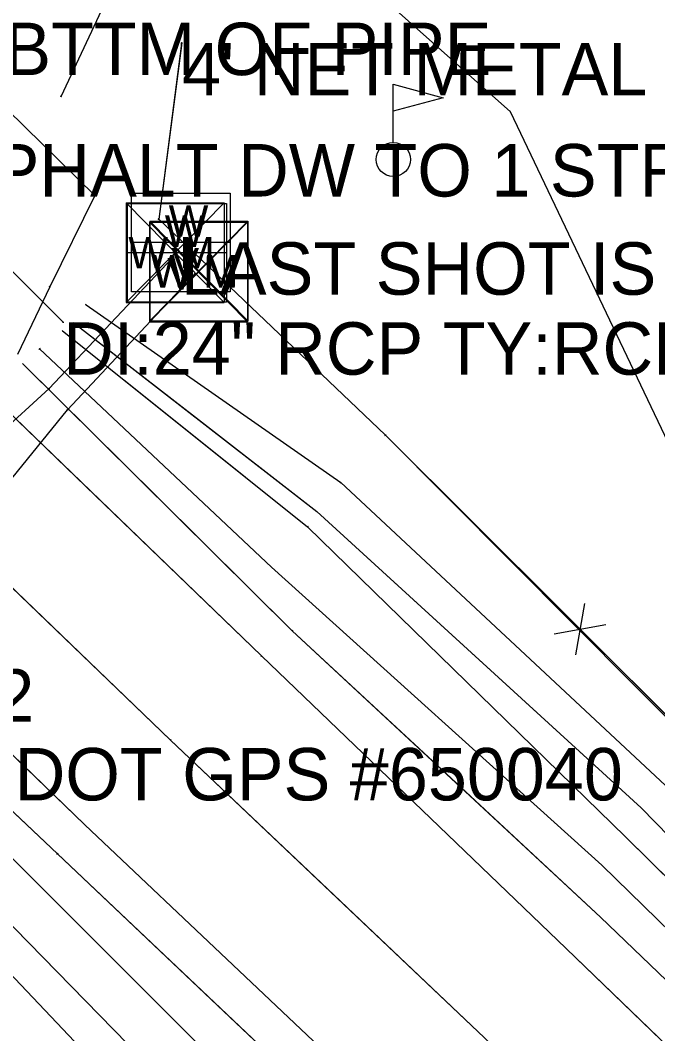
# Model space of a CAD drawing. Extents: x -99999 to 591807, y -99999 to 347168.
# Drawn here: x 588252.2 to 588313, y 346221.5 to 346318.1 of the extents above; entities that cross this region are included whole.
import ezdxf

# ---------------------------------------------------------------- set-up
doc = ezdxf.new("R2010")
doc.units = 0
for name, color, linetype in [('S_BREAKLINE', 7, 'Continuous'), ('S_DITCHLINE', 7, 'Continuous'), ('S_DRG_PT_SYM', 7, 'Continuous'), ('S_DRIVEWAY', 7, 'Continuous'), ('S_EDGE_PAVEMENT', 7, 'Continuous'), ('S_FENCE', 7, 'Continuous'), ('S_FENCE_ANNOT', 7, 'Continuous'), ('S_FLAG_POLE', 7, 'Continuous'), ('S_GRD_PT_SYM', 7, 'Continuous'), ('S_MSC_PT_SYM', 7, 'Continuous'), ('S_PAVEMENT_CROWN', 7, 'Continuous'), ('S_PRIMARY_CTL_ANNOT', 7, 'Continuous'), ('S_RDW_PT_SYM', 7, 'Continuous'), ('S_SHOULDER', 7, 'Continuous'), ('S_SIDE_DRAIN', 7, 'Continuous'), ('S_SIDE_DRAIN_ANNOT', 7, 'Continuous'), ('S_SURVEY_TEXT_ANNOT', 7, 'Continuous'), ('S_UTL_PT_SYM', 7, 'Continuous'), ('S_WATER_UTILITIES', 7, 'Continuous'), ('S_WATER_UTILITIES_ANNOT', 7, 'Continuous')]:
    doc.layers.add(name, color=color, linetype=linetype)

msp = doc.modelspace()

# ---------------------------------------------------------------- linework, layer by layer
at = {"layer": 'S_BREAKLINE'}
for points in [[(587985.007, 346494.142), (588043.408, 346436.277), (588108.559, 346374.608), (588173.852, 346311.357), (588242.383, 346247.25), (588302.697, 346186.986), (588369.158, 346122.224), (588383.207, 346097.167), (588432.308, 346045.452), (588485.71, 345983.723), (588533.051, 345919.601)], [(587978.947, 346487.853), (588038.255, 346431.024), (588103.615, 346368.923), (588168.93, 346306.428), (588237.999, 346241.179), (588296.132, 346179.846), (588360.541, 346112.54), (588377.938, 346092.952), (588425.834, 346037.788), (588477.63, 345977.565), (588525.633, 345916.464)], [(588270.945, 346334.356), (588298.929, 346309.423), (588316.919, 346271.712), (588387.51, 346208.813), (588441.295, 346152.589), (588498.26, 346098.506), (588551.789, 346050.318), (588556.498, 346044.431)], [(588267.583, 346315.916), (588265.419, 346299.156), (588287.028, 346278.583), (588316.874, 346248.579), (588343.915, 346221.838), (588373.42, 346192.774), (588395.235, 346170.529), (588420.015, 346145.892), (588449.803, 346115.64), (588486.713, 346078.801), (588522.482, 346044.903), (588554.838, 346014.155), (588576.029, 345995.146)], [(588258.499, 346290.999), (588282.77, 346274.06), (588314.166, 346244.765), (588341.56, 346217.857), (588369.119, 346190.732), (588392.899, 346168.316), (588418.339, 346141.705), (588447.624, 346113.302), (588484.571, 346076.998), (588520.035, 346043.233), (588550.34, 346012.541), (588575.477, 345989.737), (588578.825, 345983.151)], [(588254.073, 346286.789), (588276.179, 346265.976), (588307.663, 346237.576), (588332.885, 346212.93), (588360.879, 346185.108), (588386.622, 346162.852), (588413.054, 346137.046), (588442.353, 346107.702), (588480.664, 346072.643), (588515.171, 346038.537), (588542.869, 346006.756), (588564.232, 345981.492), (588590.975, 345941.879), (588596.766, 345935.725)]]:
    msp.add_lwpolyline(points, dxfattribs=at)
at = {"layer": 'S_DITCHLINE'}
for points in [[(587981.381, 346490.489), (588040.721, 346433.289), (588105.81, 346371.994), (588170.92, 346308.422), (588239.535, 346243.967), (588298.867, 346183.241), (588365.047, 346118.269), (588381.602, 346095.516), (588429.365, 346040.978), (588482.843, 345982.856), (588529.718, 345920.184), (588552.998, 345879.12), (588569.51, 345828.652), (588585.869, 345761.878), (588598.499, 345693.111), (588612.58, 345591.707), (588620.738, 345530.501), (588634.946, 345464.485), (588639.413, 345427.117), (588638.596, 345425.107)], [(588154.643, 346324.315), (588170.92, 346308.422), (588188.074, 346292.308), (588205.228, 346276.194), (588222.381, 346260.081), (588239.535, 346243.967), (588254.368, 346228.786), (588269.201, 346213.604), (588284.034, 346198.423), (588298.867, 346183.241), (588315.412, 346166.998), (588331.957, 346150.755), (588348.502, 346134.512), (588365.047, 346118.269), (588373.324, 346106.893)], [(588256.25, 346288.517), (588279.619, 346269.831), (588309.927, 346240.279), (588334.152, 346216.38), (588364.162, 346188.465), (588374.07, 346176.5), (588389.177, 346164.467), (588414.617, 346138.085), (588443.666, 346108.884), (588482.064, 346074.03), (588517.386, 346040.35), (588546.168, 346009.017), (588569.054, 345985.248), (588580.187, 345969.799), (588596.13, 345945.066), (588601.107, 345940.145)], [(588256.25, 346288.517), (588267.934, 346279.174), (588279.619, 346269.831), (588294.773, 346255.055), (588309.927, 346240.279), (588322.039, 346228.33), (588334.152, 346216.38), (588349.157, 346202.423), (588364.162, 346188.465), (588374.07, 346176.5)], [(588257.348, 346289.253), (588280.504, 346271.298), (588311.415, 346243.027), (588335.923, 346217.957), (588365.97, 346190.072), (588375.966, 346178.271), (588390.647, 346166.994), (588416.359, 346140.222), (588445.778, 346111.154), (588483.301, 346075.522), (588519.201, 346042.047), (588548.233, 346010.867), (588571.043, 345986.23), (588581.118, 345970.703), (588597.815, 345946.583), (588601.9, 345941.764), (588631.023, 345942.625), (588635.559, 345948.641), (588633.328, 345950.725), (588636.714, 345965.196), (588640.069, 345982.317), (588641.424, 345998.377)], [(588257.348, 346289.253), (588268.926, 346280.276), (588280.504, 346271.298), (588295.959, 346257.163), (588311.415, 346243.027), (588323.669, 346230.492), (588335.923, 346217.957), (588350.946, 346204.014), (588365.97, 346190.072), (588375.966, 346178.271)]]:
    msp.add_lwpolyline(points, dxfattribs=at)
at = {"layer": 'S_DRG_PT_SYM'}
msp.add_lwpolyline([(588256.311, 346289.338), (588256.311, 346289.388), (588256.311, 346289.338), (588256.261, 346289.338), (588256.311, 346289.338), (588256.311, 346289.288), (588256.311, 346289.338), (588256.361, 346289.338)], dxfattribs=at)
at = {"layer": 'S_DRIVEWAY'}
for points in [[(588256.111, 346310.878), (588262.684, 346324.856), (588278.363, 346353.936), (588300.6, 346391.67), (588311.856, 346406.55)], [(588256.111, 346310.878), (588262.684, 346324.856), (588270.523, 346339.396), (588278.363, 346353.936), (588289.481, 346372.803), (588300.6, 346391.67), (588311.856, 346406.55)], [(588224.078, 346312.27), (588231.601, 346312.394), (588239.988, 346317.557), (588249.265, 346311.269), (588259.341, 346301.433), (588255.039, 346292.72), (588251.962, 346286.264)], [(588224.078, 346312.27), (588231.601, 346312.394), (588239.988, 346317.557), (588249.265, 346311.269), (588259.341, 346301.433), (588255.039, 346292.72), (588251.962, 346286.264)]]:
    msp.add_lwpolyline(points, dxfattribs=at)
at = {"layer": 'S_EDGE_PAVEMENT'}
for points in [[(588006.506, 346515.665), (588037.252, 346486.281), (588068.965, 346456.074), (588098.412, 346427.99), (588126.486, 346401.048), (588156.062, 346372.419), (588184.379, 346345.174), (588213.093, 346317.554), (588241.735, 346289.831), (588275.211, 346257.515), (588304.275, 346229.616), (588334.125, 346200.795), (588363.948, 346171.697), (588391.179, 346144.843), (588419.554, 346117.127), (588447.946, 346088.704), (588472.864, 346062.771), (588495.2, 346037.929), (588515.958, 346012.839), (588538.304, 345983.933), (588553.852, 345961.476), (588569.437, 345935.938), (588581.549, 345913.628)], [(587990.039, 346499.659), (588021.444, 346469.827), (588052.982, 346439.412), (588082.26, 346411.475), (588110.157, 346384.471), (588139.714, 346355.894), (588167.475, 346329.092), (588196.939, 346300.739), (588228.679, 346270.069), (588258.368, 346241.406), (588287.791, 346213.567), (588317.296, 346184.82), (588347.777, 346154.949), (588374.652, 346128.542), (588403.229, 346100.418), (588430.525, 346072.999), (588454.75, 346047.655), (588476.4, 346023.753), (588497.807, 345997.867), (588518.495, 345970.798), (588533.243, 345949.774), (588549.253, 345924.479)], [(588198.736, 346331.364), (588213.093, 346317.554), (588227.414, 346303.693), (588241.735, 346289.831), (588258.473, 346273.673), (588275.211, 346257.515), (588289.743, 346243.566), (588304.275, 346229.616), (588319.2, 346215.206), (588334.125, 346200.795), (588349.036, 346186.246), (588363.948, 346171.697), (588377.564, 346158.27)], [(588167.475, 346329.092), (588182.207, 346314.916), (588196.939, 346300.739), (588212.809, 346285.404), (588228.679, 346270.069), (588243.524, 346255.738), (588258.368, 346241.406), (588273.08, 346227.487), (588287.791, 346213.567), (588302.544, 346199.194), (588317.296, 346184.82), (588332.537, 346169.885), (588347.777, 346154.949), (588361.215, 346141.746), (588374.652, 346128.542)]]:
    msp.add_lwpolyline(points, dxfattribs=at)
at = {"layer": 'S_FENCE'}
for p, q in [((588267.635, 346315.977), (588265.419, 346299.156)), ((588265.419, 346299.156), (588287.038, 346278.585)), ((588287.038, 346278.585), (588343.905, 346221.84)), ((588306.022, 346262.534), (588305.159, 346257.609)), ((588303.129, 346259.635), (588308.052, 346260.509))]:
    msp.add_line(p, q, dxfattribs=at)
for points in [[(588267.635, 346315.977), (588265.419, 346299.156)], [(588265.419, 346299.156), (588287.038, 346278.585)], [(588287.038, 346278.585), (588303.904, 346261.755)], [(588307.277, 346258.389), (588341.009, 346224.729)]]:
    msp.add_lwpolyline(points, dxfattribs=at)
at = {"layer": 'S_FLAG_POLE'}
for p, q in [((588287.783, 346306.488), (588287.783, 346312.029)), ((588287.783, 346312.029), (588292.55, 346310.75)), ((588292.55, 346310.75), (588287.783, 346309.472))]:
    msp.add_line(p, q, dxfattribs=at)
msp.add_circle((588287.783, 346304.86), 1.628, dxfattribs=at)
at = {"layer": 'S_GRD_PT_SYM'}
for points in [[(588267.583, 346315.916), (588267.632, 346315.91), (588267.583, 346315.916), (588267.589, 346315.966), (588267.583, 346315.916), (588267.533, 346315.923), (588267.583, 346315.916), (588267.576, 346315.867)], [(588298.929, 346309.423), (588298.974, 346309.444), (588298.929, 346309.423), (588298.908, 346309.468), (588298.929, 346309.423), (588298.884, 346309.401), (588298.929, 346309.423), (588298.951, 346309.378)], [(588265.419, 346299.156), (588265.453, 346299.192), (588265.419, 346299.156), (588265.382, 346299.191), (588265.419, 346299.156), (588265.384, 346299.12), (588265.419, 346299.156), (588265.455, 346299.122)], [(588258.499, 346290.999), (588258.528, 346291.041), (588258.499, 346290.999), (588258.458, 346291.028), (588258.499, 346290.999), (588258.471, 346290.958), (588258.499, 346290.999), (588258.54, 346290.971)], [(588256.25, 346288.517), (588256.281, 346288.556), (588256.25, 346288.517), (588256.211, 346288.549), (588256.25, 346288.517), (588256.219, 346288.478), (588256.25, 346288.517), (588256.289, 346288.486)], [(588257.348, 346289.253), (588257.379, 346289.293), (588257.348, 346289.253), (588257.309, 346289.284), (588257.348, 346289.253), (588257.318, 346289.214), (588257.348, 346289.253), (588257.388, 346289.223)], [(588254.073, 346286.789), (588254.107, 346286.826), (588254.073, 346286.789), (588254.037, 346286.823), (588254.073, 346286.789), (588254.039, 346286.753), (588254.073, 346286.789), (588254.109, 346286.755)], [(588287.028, 346278.583), (588287.064, 346278.618), (588287.028, 346278.583), (588286.993, 346278.618), (588287.028, 346278.583), (588286.993, 346278.547), (588287.028, 346278.583), (588287.064, 346278.547)], [(588282.77, 346274.06), (588282.804, 346274.097), (588282.77, 346274.06), (588282.733, 346274.094), (588282.77, 346274.06), (588282.736, 346274.024), (588282.77, 346274.06), (588282.807, 346274.026)], [(588280.504, 346271.298), (588280.538, 346271.335), (588280.504, 346271.298), (588280.467, 346271.332), (588280.504, 346271.298), (588280.47, 346271.261), (588280.504, 346271.298), (588280.541, 346271.264)], [(588279.619, 346269.831), (588279.654, 346269.867), (588279.619, 346269.831), (588279.583, 346269.866), (588279.619, 346269.831), (588279.584, 346269.795), (588279.619, 346269.831), (588279.654, 346269.796)], [(588276.179, 346265.976), (588276.213, 346266.013), (588276.179, 346265.976), (588276.142, 346266.009), (588276.179, 346265.976), (588276.146, 346265.939), (588276.179, 346265.976), (588276.217, 346265.942)], [(588311.415, 346243.027), (588311.451, 346243.062), (588311.415, 346243.027), (588311.38, 346243.063), (588311.415, 346243.027), (588311.379, 346242.992), (588311.415, 346243.027), (588311.45, 346242.991)], [(588309.927, 346240.279), (588309.962, 346240.315), (588309.927, 346240.279), (588309.891, 346240.314), (588309.927, 346240.279), (588309.892, 346240.243), (588309.927, 346240.279), (588309.962, 346240.244)], [(588307.663, 346237.576), (588307.698, 346237.612), (588307.663, 346237.576), (588307.627, 346237.611), (588307.663, 346237.576), (588307.628, 346237.54), (588307.663, 346237.576), (588307.698, 346237.541)]]:
    msp.add_lwpolyline(points, close=True, dxfattribs=at)
at = {"layer": 'S_MSC_PT_SYM'}
for points in [[(588267.635, 346315.977), (588267.635, 346316.027), (588267.635, 346315.977), (588267.585, 346315.977), (588267.635, 346315.977), (588267.635, 346315.927), (588267.635, 346315.977), (588267.685, 346315.977)], [(588265.419, 346299.156), (588265.419, 346299.206), (588265.419, 346299.156), (588265.369, 346299.156), (588265.419, 346299.156), (588265.419, 346299.106), (588265.419, 346299.156), (588265.469, 346299.156)], [(588287.038, 346278.585), (588287.038, 346278.635), (588287.038, 346278.585), (588286.988, 346278.585), (588287.038, 346278.585), (588287.038, 346278.535), (588287.038, 346278.585), (588287.088, 346278.585)]]:
    msp.add_lwpolyline(points, dxfattribs=at)
at = {"layer": 'S_PAVEMENT_CROWN'}
for points in [[(587997.944, 346508.04), (588029.706, 346477.772), (588061.361, 346447.919), (588091.093, 346419.114), (588118.074, 346392.844), (588147.792, 346363.812), (588175.772, 346337.118), (588205.846, 346308.092), (588236.225, 346278.658), (588266.547, 346249.5), (588296.482, 346221.112), (588325.949, 346192.27), (588355.725, 346163.525), (588383.279, 346136.413), (588411.182, 346108.722), (588439.242, 346080.601), (588464.531, 346055.005), (588485.922, 346030.52), (588506.558, 346005.755), (588528.338, 345977.311), (588543.876, 345955.523), (588560.06, 345929.961), (588571.313, 345908.674)], [(588190.809, 346322.605), (588205.846, 346308.092), (588221.035, 346293.375), (588236.225, 346278.658), (588251.386, 346264.079), (588266.547, 346249.5), (588281.514, 346235.306), (588296.482, 346221.112), (588311.215, 346206.691), (588325.949, 346192.27), (588340.837, 346177.897), (588355.725, 346163.525), (588369.502, 346149.969), (588383.279, 346136.413)]]:
    msp.add_lwpolyline(points, dxfattribs=at)
at = {"layer": 'S_RDW_PT_SYM'}
for points in [[(588256.111, 346310.878), (588256.066, 346310.899), (588256.111, 346310.878), (588256.09, 346310.833), (588256.111, 346310.878), (588256.156, 346310.857), (588256.111, 346310.878), (588256.132, 346310.923)], [(588259.341, 346301.433), (588259.386, 346301.411), (588259.341, 346301.433), (588259.363, 346301.478), (588259.341, 346301.433), (588259.296, 346301.455), (588259.341, 346301.433), (588259.319, 346301.388)], [(588255.039, 346292.72), (588255.084, 346292.698), (588255.039, 346292.72), (588255.061, 346292.765), (588255.039, 346292.72), (588254.994, 346292.741), (588255.039, 346292.72), (588255.017, 346292.674)], [(588252.478, 346285.371), (588252.513, 346285.407), (588252.478, 346285.371), (588252.442, 346285.406), (588252.478, 346285.371), (588252.443, 346285.336), (588252.478, 346285.371), (588252.513, 346285.336)], [(588278.158, 346259.92), (588278.192, 346259.957), (588278.158, 346259.92), (588278.121, 346259.954), (588278.158, 346259.92), (588278.124, 346259.884), (588278.158, 346259.92), (588278.194, 346259.886)], [(588275.211, 346257.515), (588275.246, 346257.551), (588275.211, 346257.515), (588275.175, 346257.55), (588275.211, 346257.515), (588275.177, 346257.479), (588275.211, 346257.515), (588275.247, 346257.481)], [(588266.547, 346249.5), (588266.581, 346249.536), (588266.547, 346249.5), (588266.511, 346249.534), (588266.547, 346249.5), (588266.512, 346249.463), (588266.547, 346249.5), (588266.583, 346249.465)], [(588258.368, 346241.406), (588258.403, 346241.442), (588258.368, 346241.406), (588258.332, 346241.44), (588258.368, 346241.406), (588258.334, 346241.37), (588258.368, 346241.406), (588258.405, 346241.372)], [(588255.759, 346238.662), (588255.793, 346238.698), (588255.759, 346238.662), (588255.723, 346238.696), (588255.759, 346238.662), (588255.725, 346238.626), (588255.759, 346238.662), (588255.795, 346238.628)], [(588307.53, 346232.604), (588307.564, 346232.64), (588307.53, 346232.604), (588307.494, 346232.639), (588307.53, 346232.604), (588307.495, 346232.568), (588307.53, 346232.604), (588307.566, 346232.57)], [(588304.275, 346229.616), (588304.31, 346229.652), (588304.275, 346229.616), (588304.24, 346229.651), (588304.275, 346229.616), (588304.241, 346229.58), (588304.275, 346229.616), (588304.311, 346229.581)]]:
    msp.add_lwpolyline(points, close=True, dxfattribs=at)
at = {"layer": 'S_SHOULDER'}
for points in [[(587987.101, 346496.673), (588018.378, 346466.602), (588049.781, 346436.075), (588078.444, 346407.928), (588107.073, 346380.792), (588136.202, 346353.173), (588164.678, 346326.195), (588193.77, 346298.03), (588226.039, 346266.739), (588255.759, 346238.662), (588285.11, 346210.855), (588314.364, 346182.396), (588345.002, 346152.619), (588372.244, 346126.492), (588400.279, 346098.36), (588427.769, 346070.597), (588452.079, 346045.577), (588473.813, 346021.511), (588494.82, 345995.695), (588515.11, 345968.814), (588530.371, 345947.671), (588545.694, 345922.751)], [(588164.678, 346326.195), (588179.224, 346312.113), (588193.77, 346298.03), (588209.904, 346282.384), (588226.039, 346266.739), (588240.899, 346252.7), (588255.759, 346238.662), (588270.435, 346224.758), (588285.11, 346210.855), (588299.737, 346196.625), (588314.364, 346182.396), (588329.683, 346167.507), (588345.002, 346152.619), (588358.623, 346139.555), (588372.244, 346126.492)], [(588252.478, 346285.371), (588278.158, 346259.92), (588307.53, 346232.604), (588337.485, 346203.889), (588367.054, 346174.494), (588394.554, 346147.702), (588422.753, 346120.315), (588450.955, 346091.697), (588476.151, 346065.841), (588498.123, 346041.107), (588519.591, 346015.338), (588541.804, 345986.576), (588557.379, 345963.851), (588573.141, 345938.088), (588585.121, 345914.739)], [(588252.478, 346285.371), (588265.318, 346272.646), (588278.158, 346259.92), (588292.844, 346246.262), (588307.53, 346232.604), (588322.507, 346218.247), (588337.485, 346203.889), (588352.269, 346189.192), (588367.054, 346174.494), (588380.804, 346161.098)]]:
    msp.add_lwpolyline(points, dxfattribs=at)
at = {"layer": 'S_SIDE_DRAIN'}
msp.add_line((588256.311, 346289.338), (588227.663, 346317.906), dxfattribs=at)
at = {"layer": 'S_UTL_PT_SYM'}
for points in [[(588266.741, 346295.472), (588266.741, 346295.522), (588266.741, 346295.472), (588266.691, 346295.472), (588266.741, 346295.472), (588266.741, 346295.422), (588266.741, 346295.472), (588266.791, 346295.472)], [(588268.843, 346293.921), (588268.843, 346293.971), (588268.843, 346293.921), (588268.793, 346293.921), (588268.843, 346293.921), (588268.843, 346293.871), (588268.843, 346293.921), (588268.893, 346293.921)], [(588254.992, 346283.008), (588254.992, 346283.058), (588254.992, 346283.008), (588254.942, 346283.008), (588254.992, 346283.008), (588254.992, 346282.958), (588254.992, 346283.008), (588255.042, 346283.008)], [(588256.727, 346280.978), (588256.727, 346281.028), (588256.727, 346280.978), (588256.677, 346280.978), (588256.727, 346280.978), (588256.727, 346280.928), (588256.727, 346280.978), (588256.777, 346280.978)]]:
    msp.add_lwpolyline(points, dxfattribs=at)
at = {"layer": 'S_WATER_UTILITIES'}
for p, q in [((588262.82, 346301.653), (588272.236, 346301.653)), ((588262.82, 346292.236), (588262.82, 346301.653)), ((588272.236, 346301.653), (588272.236, 346292.236)), ((588262.316, 346300.713), (588271.655, 346300.713)), ((588262.316, 346300.713), (588262.316, 346291.219)), ((588262.316, 346300.713), (588271.655, 346291.219)), ((588271.655, 346300.713), (588262.316, 346291.219)), ((588262.453, 346300.678), (588271.869, 346300.678)), ((588262.453, 346291.261), (588262.453, 346300.678)), ((588271.655, 346300.713), (588271.655, 346291.219)), ((588271.869, 346300.678), (588271.869, 346291.261)), ((588264.546, 346298.869), (588273.885, 346298.869)), ((588264.546, 346298.869), (588264.546, 346289.375)), ((588264.546, 346298.869), (588273.885, 346289.375)), ((588273.885, 346298.869), (588264.546, 346289.375)), ((588264.58, 346298.975), (588273.918, 346298.975)), ((588264.58, 346298.975), (588264.58, 346289.481)), ((588264.58, 346298.975), (588273.918, 346289.481)), ((588273.918, 346298.975), (588264.58, 346289.481)), ((588273.885, 346298.869), (588273.885, 346289.375)), ((588273.918, 346298.975), (588273.918, 346289.481)), ((588262.82, 346296.964), (588272.236, 346296.964)), ((588254.992, 346283.008), (588266.741, 346295.472)), ((588262.453, 346295.989), (588271.869, 346295.989)), ((588256.727, 346280.978), (588268.843, 346293.921)), ((588272.236, 346292.236), (588262.82, 346292.236)), ((588262.316, 346291.219), (588271.655, 346291.219)), ((588271.869, 346291.261), (588262.453, 346291.261)), ((588264.58, 346289.481), (588273.918, 346289.481)), ((588264.546, 346289.375), (588273.885, 346289.375)), ((588231.32, 346261.484), (588254.992, 346283.008)), ((588236.58, 346256.237), (588256.727, 346280.978))]:
    msp.add_line(p, q, dxfattribs=at)

# ---------------------------------------------------------------- texts
at = {"layer": 'S_FENCE_ANNOT'}
msp.add_text("4' NET METAL POST 1 BARB", height=5, dxfattribs=at).set_placement((588267.635, 346310.977))
at = {"layer": 'S_PRIMARY_CTL_ANNOT'}
for s, p in [('PN:102', (588231.257, 346251.242)), ('PD:ARDOT GPS #650040', (588231.257, 346243.742))]:
    msp.add_text(s, height=5, dxfattribs=at).set_placement(p)
at = {"layer": 'S_SIDE_DRAIN_ANNOT'}
for s, p in [('CN:0% BTTM OF PIPE', (588227.663, 346312.906)), ('DI:24" RCP TY:RCP CN:0% BTTM OF', (588256.311, 346284.338))]:
    msp.add_text(s, height=5, dxfattribs=at).set_placement(p)
at = {"layer": 'S_SURVEY_TEXT_ANNOT'}
msp.add_text('ASPHALT DW TO 1 STRY WOOD FRAME', height=5, dxfattribs=at).set_placement((588240.667, 346301.33))
at = {"layer": 'S_WATER_UTILITIES'}
for s, p in [('W', (588266.37, 346297.495)), ('W', (588266.003, 346296.52)), ('W M', (588262.521, 346294.479)), ('V', (588266.607, 346293.432)), ('W M', (588264.751, 346292.635)), ('W M', (588264.784, 346292.741)), ('V', (588266.24, 346292.457))]:
    msp.add_text(s, height=3, rotation=360, dxfattribs=at).set_placement(p)
at = {"layer": 'S_WATER_UTILITIES_ANNOT'}
msp.add_text('LAST SHOT IS WMETER', height=5, dxfattribs=at).set_placement((588267.528, 346291.964))

doc.saveas('drawing.dxf')
